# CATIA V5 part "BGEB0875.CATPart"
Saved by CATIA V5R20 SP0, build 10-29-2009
Part number: BGEB0875
Revision: 4
Definition: design
Nomenclature: BGEB0875
Source: made
Description: NOT SPECIFIED
Bounding box of the stored display mesh (mm): x -19.71 to 19.71, y -19.71 to 19.71, z -16.002 to 28.448
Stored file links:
  C:\Users\Utente\Desktop\3D files BGEB\BGEB0875.CATPart
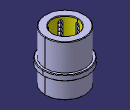
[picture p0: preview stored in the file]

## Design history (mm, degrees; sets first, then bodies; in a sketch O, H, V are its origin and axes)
Body1 "MANIFOLD_SOLID_BREP #38" (main body)
  Solid1: solid without history
Body2 "MANIFOLD_SOLID_BREP #76"
  Solid2: solid without history
Body3 "MANIFOLD_SOLID_BREP #114"
  Solid3: solid without history
Body4 "MANIFOLD_SOLID_BREP #152"
  Solid4: solid without history
Body5 "MANIFOLD_SOLID_BREP #190"
  Solid5: solid without history
Body6 "MANIFOLD_SOLID_BREP #228"
  Solid6: solid without history
Body7 "MANIFOLD_SOLID_BREP #266"
  Solid7: solid without history
Body8 "MANIFOLD_SOLID_BREP #304"
  Solid8: solid without history
Body9 "MANIFOLD_SOLID_BREP #2014"
  Solid9: solid without history
Body10 "MANIFOLD_SOLID_BREP #2052"
  Solid10: solid without history
Body11 "MANIFOLD_SOLID_BREP #2090"
  Solid11: solid without history
Body12 "MANIFOLD_SOLID_BREP #2128"
  Solid12: solid without history
Body13 "MANIFOLD_SOLID_BREP #2166"
  Solid13: solid without history
Body14 "MANIFOLD_SOLID_BREP #2204"
  Solid14: solid without history
Body15 "MANIFOLD_SOLID_BREP #2242"
  Solid15: solid without history
Body16 "MANIFOLD_SOLID_BREP #2280"
  Solid16: solid without history
Body17 "MANIFOLD_SOLID_BREP #2318"
  Solid17: solid without history
Body18 "MANIFOLD_SOLID_BREP #2356"
  Solid18: solid without history
Body19 "MANIFOLD_SOLID_BREP #2394"
  Solid19: solid without history
Body20 "MANIFOLD_SOLID_BREP #2432"
  Solid20: solid without history
Body21 "MANIFOLD_SOLID_BREP #2470"
  Solid21: solid without history
Body22 "MANIFOLD_SOLID_BREP #2508"
  Solid22: solid without history
Body23 "MANIFOLD_SOLID_BREP #2546"
  Solid23: solid without history
Body24 "MANIFOLD_SOLID_BREP #2584"
  Solid24: solid without history
Body25 "MANIFOLD_SOLID_BREP #2622"
  Solid25: solid without history
Body26 "MANIFOLD_SOLID_BREP #2660"
  Solid26: solid without history
Body27 "MANIFOLD_SOLID_BREP #2698"
  Solid27: solid without history
Body28 "MANIFOLD_SOLID_BREP #2736"
  Solid28: solid without history
Body29 "MANIFOLD_SOLID_BREP #2774"
  Solid29: solid without history
Body30 "MANIFOLD_SOLID_BREP #2812"
  Solid30: solid without history
Body31 "MANIFOLD_SOLID_BREP #2850"
  Solid31: solid without history
Body32 "MANIFOLD_SOLID_BREP #2888"
  Solid32: solid without history
Body33 "MANIFOLD_SOLID_BREP #2926"
  Solid33: solid without history
Body34 "MANIFOLD_SOLID_BREP #2964"
  Solid34: solid without history
Body35 "MANIFOLD_SOLID_BREP #3002"
  Solid35: solid without history
Body36 "MANIFOLD_SOLID_BREP #3040"
  Solid36: solid without history
Body37 "MANIFOLD_SOLID_BREP #3078"
  Solid37: solid without history
Body38 "MANIFOLD_SOLID_BREP #3116"
  Solid38: solid without history
Body39 "MANIFOLD_SOLID_BREP #3154"
  Solid39: solid without history
Body40 "MANIFOLD_SOLID_BREP #3192"
  Solid40: solid without history
Body41 "MANIFOLD_SOLID_BREP #3230"
  Solid41: solid without history
Body42 "MANIFOLD_SOLID_BREP #3268"
  Solid42: solid without history
Body43 "MANIFOLD_SOLID_BREP #3306"
  Solid43: solid without history
Body44 "MANIFOLD_SOLID_BREP #3344"
  Solid44: solid without history
Body45 "MANIFOLD_SOLID_BREP #3382"
  Solid45: solid without history
Body46 "MANIFOLD_SOLID_BREP #3420"
  Solid46: solid without history
Body47 "MANIFOLD_SOLID_BREP #3458"
  Solid47: solid without history
Body48 "MANIFOLD_SOLID_BREP #3496"
  Solid48: solid without history
Body49 "MANIFOLD_SOLID_BREP #3534"
  Solid49: solid without history
Body50 "MANIFOLD_SOLID_BREP #3572"
  Solid50: solid without history
Body51 "MANIFOLD_SOLID_BREP #3610"
  Solid51: solid without history
Body52 "MANIFOLD_SOLID_BREP #3648"
  Solid52: solid without history
Body53 "MANIFOLD_SOLID_BREP #3686"
  Solid53: solid without history
Body54 "MANIFOLD_SOLID_BREP #3724"
  Solid54: solid without history
Body55 "MANIFOLD_SOLID_BREP #3762"
  Solid55: solid without history
Body56 "MANIFOLD_SOLID_BREP #3800"
  Solid56: solid without history
Body57 "MANIFOLD_SOLID_BREP #3838"
  Solid57: solid without history
Body58 "MANIFOLD_SOLID_BREP #3876"
  Solid58: solid without history
Body59 "MANIFOLD_SOLID_BREP #3914"
  Solid59: solid without history
Body60 "MANIFOLD_SOLID_BREP #3952"
  Solid60: solid without history
Body61 "MANIFOLD_SOLID_BREP #3990"
  Solid61: solid without history
Body62 "MANIFOLD_SOLID_BREP #4028"
  Solid62: solid without history
Body63 "MANIFOLD_SOLID_BREP #4066"
  Solid63: solid without history
Body64 "MANIFOLD_SOLID_BREP #4104"
  Solid64: solid without history
Body65 "MANIFOLD_SOLID_BREP #4142"
  Solid65: solid without history
Body66 "MANIFOLD_SOLID_BREP #4180"
  Solid66: solid without history
Body67 "MANIFOLD_SOLID_BREP #4218"
  Solid67: solid without history
Body68 "MANIFOLD_SOLID_BREP #4256"
  Solid68: solid without history
Body69 "MANIFOLD_SOLID_BREP #4294"
  Solid69: solid without history
Body70 "MANIFOLD_SOLID_BREP #4332"
  Solid70: solid without history
Body71 "MANIFOLD_SOLID_BREP #4370"
  Solid71: solid without history
Body72 "MANIFOLD_SOLID_BREP #4408"
  Solid72: solid without history
Body73 "MANIFOLD_SOLID_BREP #4446"
  Solid73: solid without history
